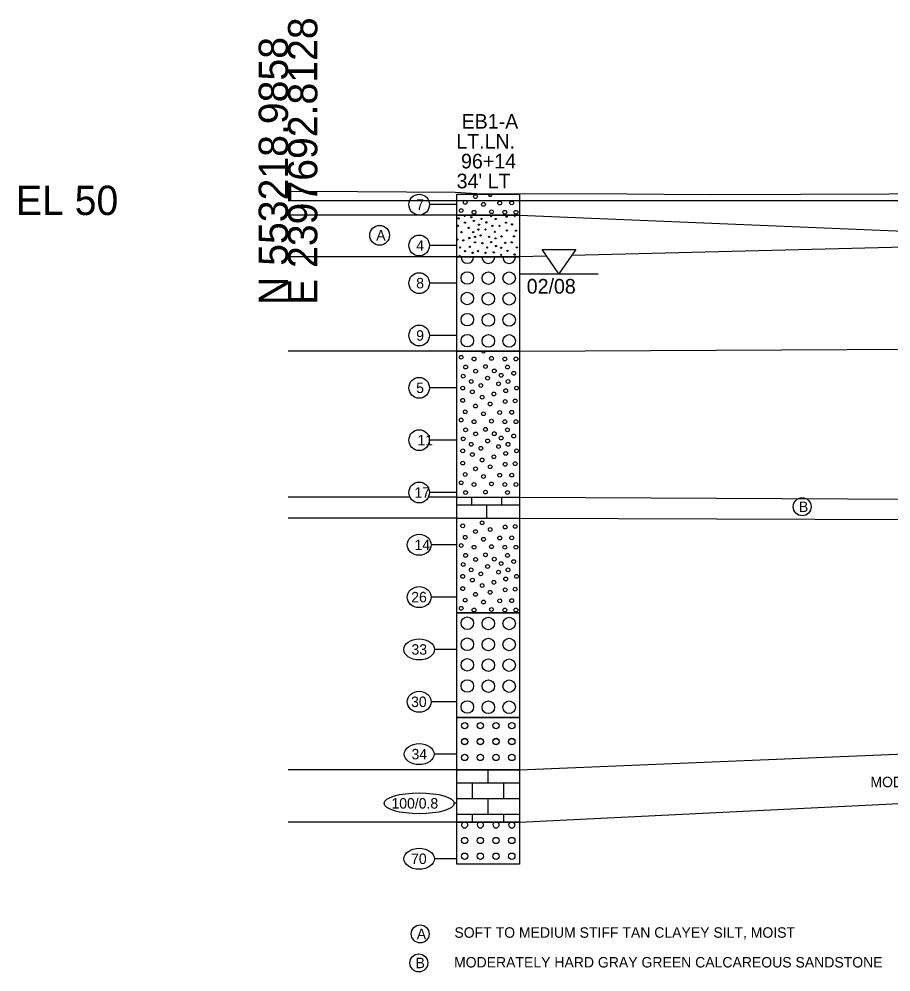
# Model space of a CAD drawing. Extents: x -26 to 164, y -74 to 517.
# Drawn here: x -25.7 to 57.6, y -73.7 to 17.3 of the extents above; entities that cross this region are included whole.
import ezdxf

# ---------------------------------------------------------------- set-up
doc = ezdxf.new("R2010")
doc.units = 0
for name, color, linetype in [('Default', 7, 'Continuous'), ('Exist XS Ground Line', 7, 'Continuous'), ('Old_Level_63', 7, 'Continuous'), ('Prop Road Sect_ Boring - Header Labels from Geopak', 7, 'Continuous'), ('Prop Road Sect_ Boring - Material (Outline)', 7, 'Continuous'), ('Prop Road Sect_ Boring - Peripheral (24 Hr GrdWtr Date)', 7, 'Continuous'), ('Prop Road Sect_ Boring - Peripheral (SPT Oval + Leader)', 7, 'Continuous'), ('Prop Road Sect_ Boring - Peripheral (SPT Tx)', 7, 'Continuous'), ('Prop Road Sect_ Material - Contact (General - Minor)', 7, 'Continuous'), ('Prop Road Sect_ Material - Tx (Composite Desc)', 7, 'Continuous'), ('Water Mark (24 Hr) Cell', 7, 'Continuous')]:
    doc.layers.add(name, color=color, linetype=linetype)

msp = doc.modelspace()

# ---------------------------------------------------------------- linework, layer by layer
at = {"layer": 'Default'}
for p, q in [((16.115, -28.358), (22.186, -28.358)), ((16.115, -30.381), (22.186, -30.381)), ((19.122, -55.666), (19.122, -54.412)), ((16.128, -55.666), (22.122, -55.666)), ((17.622, -57.165), (17.622, -55.666)), ((20.622, -57.165), (20.622, -55.666)), ((22.125, -55.666), (22.128, -55.666)), ((16.128, -57.165), (22.122, -57.165)), ((19.122, -58.663), (19.122, -57.165)), ((22.125, -57.165), (22.128, -57.165)), ((16.128, -58.663), (22.122, -58.663)), ((17.622, -59.412), (17.622, -58.663)), ((20.622, -59.412), (20.622, -58.663)), ((22.125, -58.663), (22.128, -58.663))]:
    msp.add_line(p, q, dxfattribs=at)
for centre, radius in [((16.302, -1.725), 0.06), ((17.502, -1.617), 0.06), ((18.483, -1.779), 0.06), ((19.407, -1.509), 0.06), ((19.845, -1.779), 0.06), ((20.88, -1.563), 0.06), ((16.248, -2.433), 0.06), ((16.902, -2.133), 0.06), ((17.256, -2.625), 0.06), ((17.748, -1.971), 0.06), ((18.183, -2.787), 0.06), ((18.237, -2.325), 0.06), ((18.864, -2.787), 0.06), ((18.945, -2.106), 0.06), ((19.518, -2.433), 0.06), ((20.199, -2.433), 0.06), ((20.823, -2.133), 0.06), ((21.396, -2.298), 0.06), ((16.575, -3.033), 0.06), ((17.31, -3.606), 0.06), ((17.691, -3.033), 0.06), ((17.856, -3.495), 0.06), ((18.399, -3.36), 0.06), ((19.218, -3.495), 0.06), ((19.761, -3.006), 0.06), ((19.815, -3.633), 0.06), ((20.388, -3.441), 0.06), ((20.907, -2.871), 0.06), ((21.588, -3.441), 0.06), ((21.777, -2.898), 0.06), ((16.194, -3.741), 0.06), ((16.44, -4.503), 0.06), ((16.74, -3.822), 0.06), ((17.367, -4.449), 0.06), ((17.856, -4.014), 0.06), ((18.564, -4.095), 0.06), ((19.026, -4.503), 0.06), ((19.407, -3.987), 0.06), ((19.872, -4.368), 0.06), ((20.361, -4.53), 0.06), ((20.742, -4.068), 0.06), ((21.369, -4.014), 0.06), ((21.853, -4.493), 0.06), ((16.386, -5.34), 0.06), ((16.902, -4.857), 0.06), ((17.636, -5.004), 0.06), ((18.156, -4.857), 0.06), ((18.864, -5.022), 0.06), ((19.653, -4.968), 0.06), ((20.361, -5.211), 0.06), ((20.961, -4.83), 0.06), ((21.642, -5.184), 0.06), ((17.126, -7.415), 0.6), ((19.136, -7.439), 0.6), ((21.122, -7.439), 0.6), ((17.126, -9.383), 0.6), ((21.122, -9.413), 0.6), ((17.126, -11.399), 0.6), ((21.122, -11.423), 0.6), ((17.126, -13.409), 0.6), ((21.122, -13.433), 0.6), ((16.548, -14.991), 0.18), ((17.772, -15.156), 0.18), ((19.434, -15.102), 0.18), ((20.715, -15.156), 0.18), ((21.777, -15.156), 0.18), ((16.967, -15.929), 0.18), ((17.923, -16.319), 0.18), ((18.857, -15.883), 0.18), ((19.705, -16.298), 0.18), ((20.966, -15.929), 0.18), ((21.558, -16.524), 0.18), ((16.74, -16.797), 0.18), ((17.502, -17.313), 0.18), ((19.067, -16.993), 0.18), ((20.361, -16.716), 0.18), ((21.015, -17.313), 0.18), ((16.686, -17.94), 0.18), ((17.61, -18.294), 0.18), ((18.426, -17.694), 0.18), ((20.115, -17.532), 0.18), ((20.796, -18.186), 0.18), ((21.831, -17.94), 0.18), ((16.686, -19.11), 0.18), ((18.54, -18.81), 0.18), ((19.668, -18.501), 0.18), ((20.742, -19.221), 0.18), ((21.696, -19.164), 0.18), ((16.929, -20.202), 0.18), ((17.91, -19.656), 0.18), ((19.314, -19.458), 0.18), ((16.548, -20.988), 0.18), ((18.672, -20.391), 0.18), ((19.434, -21.099), 0.18), ((20.223, -20.271), 0.18), ((21.369, -20.253), 0.18), ((16.967, -21.926), 0.18), ((17.772, -21.153), 0.18), ((18.857, -21.88), 0.18), ((20.715, -21.153), 0.18), ((20.966, -21.926), 0.18), ((21.777, -21.153), 0.18), ((16.74, -22.794), 0.18), ((17.923, -22.316), 0.18), ((19.705, -22.295), 0.18), ((20.361, -22.713), 0.18), ((21.558, -22.521), 0.18), ((18.426, -23.691), 0.18), ((19.067, -22.99), 0.18), ((20.115, -23.529), 0.18), ((21.015, -23.31), 0.18), ((16.686, -23.937), 0.18), ((17.61, -24.291), 0.18), ((19.668, -24.498), 0.18), ((20.796, -24.183), 0.18), ((21.831, -23.937), 0.18), ((16.686, -25.107), 0.18), ((17.91, -25.653), 0.18), ((18.54, -24.807), 0.18), ((19.314, -25.455), 0.18), ((20.742, -25.218), 0.18), ((21.696, -25.161), 0.18), ((16.929, -26.199), 0.18), ((18.672, -26.388), 0.18), ((20.223, -26.268), 0.18), ((21.369, -26.25), 0.18), ((16.548, -26.985), 0.18), ((17.772, -27.15), 0.18), ((19.434, -27.096), 0.18), ((20.715, -27.15), 0.18), ((21.777, -27.15), 0.18), ((16.967, -27.923), 0.18), ((18.857, -27.877), 0.18), ((20.966, -27.923), 0.18), ((16.686, -31.104), 0.18), ((18.54, -30.804), 0.18), ((17.91, -31.65), 0.18), ((19.314, -31.452), 0.18), ((20.742, -31.215), 0.18), ((21.696, -31.158), 0.18), ((16.929, -32.196), 0.18), ((18.672, -32.385), 0.18), ((20.223, -32.265), 0.18), ((21.369, -32.247), 0.18), ((16.548, -32.982), 0.18), ((17.772, -33.147), 0.18), ((19.434, -33.093), 0.18), ((20.715, -33.147), 0.18), ((21.777, -33.147), 0.18), ((16.967, -33.92), 0.18), ((17.923, -34.31), 0.18), ((18.857, -33.874), 0.18), ((19.705, -34.289), 0.18), ((20.361, -34.707), 0.18), ((20.966, -33.92), 0.18), ((21.558, -34.515), 0.18), ((16.74, -34.788), 0.18), ((17.502, -35.304), 0.18), ((18.426, -35.685), 0.18), ((19.067, -34.984), 0.18), ((20.115, -35.523), 0.18), ((21.015, -35.304), 0.18), ((16.686, -35.931), 0.18), ((17.61, -36.285), 0.18), ((19.668, -36.492), 0.18), ((20.796, -36.177), 0.18), ((21.831, -35.931), 0.18), ((16.686, -37.101), 0.18), ((18.54, -36.801), 0.18), ((19.314, -37.449), 0.18), ((20.742, -37.212), 0.18), ((21.696, -37.155), 0.18), ((16.929, -38.193), 0.18), ((17.91, -37.647), 0.18), ((18.672, -38.382), 0.18), ((20.223, -38.262), 0.18), ((21.369, -38.244), 0.18), ((16.548, -38.979), 0.18), ((17.772, -39.144), 0.18), ((19.434, -39.09), 0.18), ((20.715, -39.144), 0.18), ((21.777, -39.144), 0.18), ((17.126, -40.405), 0.6), ((19.136, -40.429), 0.6), ((21.122, -40.429), 0.6), ((17.126, -42.415), 0.6), ((19.136, -42.439), 0.6), ((21.122, -42.439), 0.6), ((17.126, -44.383), 0.6), ((19.136, -44.413), 0.6), ((21.122, -44.413), 0.6), ((17.126, -46.399), 0.6), ((19.136, -46.423), 0.6), ((21.122, -46.423), 0.6), ((17.126, -48.409), 0.6), ((19.136, -48.433), 0.6), ((21.122, -48.433), 0.6), ((16.875, -50.203), 0.3), ((18.375, -50.203), 0.3), ((19.875, -50.203), 0.3), ((21.375, -50.203), 0.3), ((16.875, -51.703), 0.3), ((16.875, -51.73), 0.3), ((18.375, -51.703), 0.3), ((18.375, -51.73), 0.3), ((19.875, -51.703), 0.3), ((19.875, -51.73), 0.3), ((21.375, -51.703), 0.3), ((21.375, -51.73), 0.3), ((16.875, -53.23), 0.3), ((18.375, -53.23), 0.3), ((19.875, -53.23), 0.3), ((21.375, -53.23), 0.3), ((16.875, -61.167), 0.3), ((18.375, -61.167), 0.3), ((19.875, -61.167), 0.3), ((21.375, -61.167), 0.3), ((16.875, -62.667), 0.3), ((18.375, -62.667), 0.3), ((19.875, -62.667), 0.3), ((21.375, -62.667), 0.3)]:
    msp.add_circle(centre, radius, dxfattribs=at)
for centre, radius, start, end in [((16.875, -1.455), 0.06, 134.14919, 45.85081), ((21.669, -1.455), 0.06, 134.14919, 45.85081), ((17.126, -5.405), 0.6, 180.65482, 359.34518), ((19.136, -5.429), 0.6, 178.36275, 1.63725), ((21.122, -5.429), 0.6, 178.36275, 1.63725), ((18.672, -14.394), 0.18, 185.82425, 354.17575), ((20.223, -14.274), 0.18, 230.18751, 309.81249), ((21.369, -14.256), 0.18, 240.24367, 299.75633), ((16.875, -59.667), 0.3, 121.90898, 58.09102), ((18.375, -59.667), 0.3, 121.90898, 58.09102), ((19.875, -59.667), 0.3, 121.90898, 58.09102), ((21.375, -59.667), 0.3, 121.90898, 58.09102)]:
    msp.add_arc(centre, radius, start, end, dxfattribs=at)
at = {"layer": 'Exist XS Ground Line'}
msp.add_lwpolyline([(0, 0.86), (1.998, 0.878), (15.974, 0.781), (18.535, 0.632), (22.599, 0.644), (32.392, 0.609), (35.94, 0.601), (40.488, 0.574), (65.866, 0.642), (67.354, 0.72), (72.128, 0.732), (80.323, 0.753), (84.267, 0.773), (110.223, 0.935), (117.286, 0.95), (128.722, 1.019), (135.066, 1.049)], dxfattribs=at)
at = {"layer": 'Old_Level_63'}
msp.add_line((0, 0), (72.128, 0), dxfattribs=at)
at = {"layer": 'Prop Road Sect_ Boring - Material (Outline)'}
for points in [[(16.128, 0.588), (22.128, 0.588), (22.128, -1.412), (16.128, -1.412)], [(16.128, -1.412), (22.128, -1.412), (22.128, -5.412), (16.128, -5.412)], [(16.128, -5.412), (22.128, -5.412), (22.128, -14.412), (16.128, -14.412)], [(16.128, -14.412), (22.128, -14.412), (22.128, -39.412), (16.128, -39.412)], [(16.128, -39.412), (22.128, -39.412), (22.128, -49.412), (16.128, -49.412)], [(16.128, -49.412), (22.128, -49.412), (22.128, -54.412), (16.128, -54.412)], [(16.128, -54.412), (22.128, -54.412), (22.128, -59.412), (16.128, -59.412)], [(16.128, -59.412), (22.128, -59.412), (22.128, -63.412), (16.128, -63.412)]]:
    msp.add_lwpolyline(points, close=True, dxfattribs=at)
for centre, radius in [((17.91, 0.353), 0.18), ((16.548, -0.979), 0.18), ((16.929, -0.193), 0.18), ((18.672, -0.382), 0.18), ((19.434, -1.09), 0.18), ((20.223, -0.262), 0.18), ((21.369, -0.244), 0.18), ((17.772, -1.144), 0.18), ((20.715, -1.144), 0.18), ((21.777, -1.144), 0.18), ((19.136, -9.413), 0.6), ((19.136, -11.423), 0.6), ((19.136, -13.433), 0.6), ((17.502, -23.31), 0.18)]:
    msp.add_circle(centre, radius, dxfattribs=at)
msp.add_arc((19.314, 0.551), 0.18, 168.2251, 11.7749, dxfattribs=at)
at = {"layer": 'Prop Road Sect_ Boring - Peripheral (SPT Oval + Leader)'}
for p, q in [((16.128, -0.412), (13.511, -0.412)), ((16.128, -4.312), (13.511, -4.312)), ((16.128, -7.912), (13.511, -7.912)), ((16.128, -12.912), (13.511, -12.912)), ((16.128, -17.912), (13.511, -17.912)), ((16.128, -22.912), (13.511, -22.912)), ((16.128, -27.912), (13.511, -27.912)), ((16.115, -29.079), (21.859, -29.079)), ((17.546, -29.079), (17.546, -28.361)), ((18.984, -30.381), (18.984, -29.079)), ((20.421, -29.079), (20.421, -28.361)), ((21.862, -29.079), (22.131, -29.079)), ((16.128, -32.912), (13.676, -32.912)), ((16.128, -37.912), (13.676, -37.912)), ((16.128, -42.912), (13.999, -42.912)), ((16.128, -47.912), (13.676, -47.912)), ((16.128, -52.912), (13.96, -52.912)), ((16.128, -57.614), (15.873, -57.614)), ((16.128, -62.912), (13.983, -62.912))]:
    msp.add_line(p, q, dxfattribs=at)
for centre, major_axis, ratio in [((12.528, -0.412), (0, 1), 0.983465), ((12.528, -4.312), (0, 1), 0.983465), ((12.528, -7.912), (0, 1), 0.983465), ((12.528, -12.912), (0, 1), 0.983465), ((12.528, -17.912), (0, 1), 0.983465), ((12.528, -22.912), (0, 1), 0.983465), ((12.528, -27.912), (0, 1), 0.983465), ((12.528, -32.912), (1.149, 0), 0.870459), ((12.528, -37.912), (1.149, 0), 0.870459), ((12.528, -42.912), (1.472, 0), 0.679508), ((12.528, -47.912), (1.149, 0), 0.870459), ((12.528, -52.912), (1.432, 0), 0.698186), ((12.528, -57.614), (3.346, 0), 0.298894), ((12.528, -62.912), (1.456, 0), 0.686858)]:
    msp.add_ellipse(centre, major_axis=major_axis, ratio=ratio, dxfattribs=at)
at = {"layer": 'Prop Road Sect_ Material - Contact (General - Minor)'}
for p, q in [((16.128, -1.412), (0, -1.412)), ((16.128, -5.412), (0, -5.412)), ((16.128, -14.412), (0, -14.412)), ((22.128, -14.412), (136.128, -13.826)), ((11.647, -28.358), (0, -28.358)), ((16.115, -28.358), (13.408, -28.358)), ((22.186, -28.358), (136.135, -28.932)), ((16.115, -30.381), (0, -30.381)), ((22.186, -30.381), (136.135, -30.731)), ((22.128, -54.412), (136.128, -49.721)), ((16.128, -54.412), (0, -54.412)), ((22.128, -59.412), (136.128, -53.826)), ((16.128, -59.412), (0, -59.412))]:
    msp.add_line(p, q, dxfattribs=at)
for points in [[(22.128, -1.412), (81.847, -3.898), (27.097, -5.269)], [(24.7, -5.329), (22.128, -5.412)]]:
    msp.add_lwpolyline(points, dxfattribs=at)
at = {"layer": 'Prop Road Sect_ Material - Tx (Composite Desc)'}
for centre, radius in [((8.75, -3.341), 0.946), ((49.114, -29.279), 0.86), ((12.624, -70.095), 0.86), ((12.495, -72.865), 0.86)]:
    msp.add_circle(centre, radius, dxfattribs=at)
at = {"layer": 'Water Mark (24 Hr) Cell'}
for p, q in [((22.128, -7.012), (25.878, -7.012)), ((25.878, -7.012), (29.628, -7.012))]:
    msp.add_line(p, q, dxfattribs=at)
msp.add_lwpolyline([(24.265, -4.706), (27.49, -4.706), (25.878, -7.012)], close=True, dxfattribs=at)

# ---------------------------------------------------------------- texts
at = {"layer": 'Old_Level_63'}
for s, p in [('E 2397692.8128', (2.8, -10)), ('N 553218.9858', (0, -10))]:
    msp.add_text(s, height=2.8, rotation=90, dxfattribs=at).set_placement(p)
msp.add_text('EL 50', height=2.8, dxfattribs=at).set_placement((-26, -1.4))
at = {"layer": 'Prop Road Sect_ Boring - Header Labels from Geopak'}
for s, p in [('EB1-A', (16.581, 6.847)), ('LT.LN.', (16.074, 4.947)), ('96+14', (16.526, 3.047)), ("34' LT", (16.107, 1.147))]:
    msp.add_text(s, height=1.4, dxfattribs=at).set_placement(p)
at = {"layer": 'Prop Road Sect_ Boring - Peripheral (24 Hr GrdWtr Date)'}
msp.add_text('02/08', height=1.4, dxfattribs=at).set_placement((22.802, -8.91))
at = {"layer": 'Prop Road Sect_ Boring - Peripheral (SPT Tx)'}
for s, p in [('7', (12.244, -0.912)), ('4', (12.244, -4.812)), ('8', (12.244, -8.412)), ('9', (12.244, -13.412)), ('5', (12.244, -18.412)), ('11', (12.362, -23.412)), ('17', (12.079, -28.412)), ('14', (12.079, -33.412)), ('26', (11.772, -38.412)), ('33', (11.795, -43.412)), ('30', (11.756, -48.412)), ('34', (11.795, -53.412)), ('100/0.8', (9.882, -58.114)), ('70', (11.756, -63.412))]:
    msp.add_text(s, height=1, dxfattribs=at).set_placement(p)
at = {"layer": 'Prop Road Sect_ Material - Tx (Composite Desc)'}
for s, p in [('A', (8.428, -3.841)), ('B', (48.807, -29.779)), ('MODERATELY HARD', (55.634, -56.073)), ('A', (12.301, -70.595)), ('SOFT TO MEDIUM STIFF TAN CLAYEY SILT, MOIST', (15.895, -70.457)), ('B', (12.187, -73.365)), ('MODERATELY HARD GRAY GREEN CALCAREOUS SANDSTONE', (15.858, -73.3))]:
    msp.add_text(s, height=1, dxfattribs=at).set_placement(p)

doc.saveas('drawing.dxf')
